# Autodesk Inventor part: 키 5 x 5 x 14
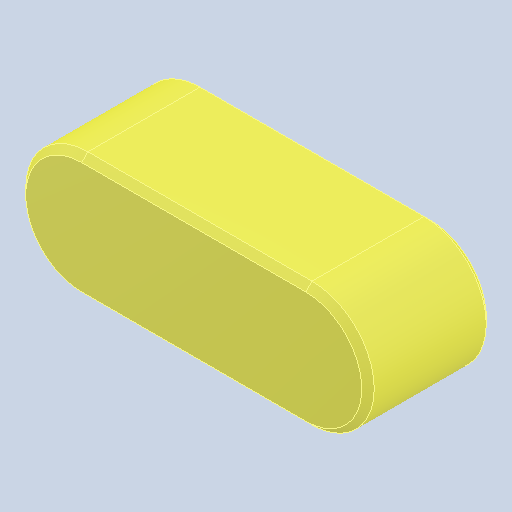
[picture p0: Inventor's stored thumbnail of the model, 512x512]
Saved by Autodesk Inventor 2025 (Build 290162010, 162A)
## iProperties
Created: 2024-07
Part Number: 키 5 x 5 x 14
Material: 강철, 연강
Description: 키 및 해당 키홈
Document SubType Name: Modeling
Designer: 학생
Density: 7.85 g/cm^3
Appearance: 기본값
Author: jhkim
Sending System: Autodesk Inventor 2025
Preprocessor: ST-DEVELOPER v20
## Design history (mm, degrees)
feature "Solid1"
node "솔리드1"
